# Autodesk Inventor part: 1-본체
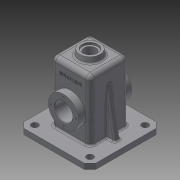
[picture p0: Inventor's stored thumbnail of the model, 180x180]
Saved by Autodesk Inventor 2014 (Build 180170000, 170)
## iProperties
Created: 2016-02
Part Number: 1-본체
Material: 일반
Document SubType Name: Modeling
Designer: 703-04
Density: 1 g/cm^3
Appearance: 기본값
Author: 703-04
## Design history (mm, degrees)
sketch "스케치1"
  geometry: L1 (-65, 65)-(65, 65); L2 (65, 65)-(65, -65); L3 (65, -65)-(-65, -65); L4 (-65, -65)-(-65, 65); 1 further point
  constraints: 8 end point, 2 parallel, 1 horizontal, 1 perpendicular
  dimensions: "d0" = 130 distance of L2.end L3.end; "d1" = 65 distance from line of point (0, 0) L4; "d2" = 65 distance from line of point (0, 0) L1; "d3" = 130 distance between parallel lines of L3 L1
extrude "돌출1" new body sketch "스케치1" distance "d4" = 10; taper "d5" = 0 deg
chamfer "모따기1" distance "d6" = 10; stored, may be unused: second distance "d7" = 2, angle "d8" = 45 deg
sketch "스케치2"
  geometry: L1 (-35, 35)-(35, 35); L2 (35, 35)-(35, -35); L3 (35, -35)-(-35, -35); L4 (-35, -35)-(-35, 35); 1 further point
  constraints: 8 end point, 2 parallel, 1 horizontal, 1 perpendicular
  dimensions: "d9" = 35 distance from line of point (0, 0) L1; "d10" = 70 distance between parallel lines of L3 L1; "d11" = 35 distance from line of point (0, 0) L4; "d12" = 70 distance between parallel lines of L2 L4
extrude "돌출2" join sketch "스케치2" distance "d13" = 110; taper "d14" = 0 deg
node "작업 평면1"
sketch "스케치4"
  geometry: L1 (0, 0)-(0, 131.974); L2 (-55, 0)-(55, 0) reference; L3 (-58, 55)-(58, 55); C1 r 27.5 at (0, 55)
  constraints: 4 end point, 1 centre point, 1 midpoint, 1 parallel, 1 perpendicular, 1 point on line
  dimensions: "d18" = 55 diameter of C1; "d19" = 55 distance between parallel lines of L2 L3
extrude "돌출3" join sketch "스케치4" stored distance "d20" = 96; taper "d21" = 0 deg
hole "구멍1" diameter "d24" = 32; stored, may be unused: countersink angle "d28" = 90 deg, drill point angle "d30" = 118 deg; dims "d22" = 10, "d23" = 10, "d25" = 6, "d26" = 4, "d27" = 2, "d29" = 8
sketch "스케치6"
  geometry: L1 (-55, 0)-(55, 0) reference; L2 (-30, 115)-(30, 115); L3 (30, 115)-(30, 0); L4 (30, 0)-(-30, 0); L5 (-30, 0)-(-30, 115); L6 (-35, 10)-(-35, 120) reference; L7 (35, 120)-(-35, 120) reference; L8 (35, 10)-(35, 120) reference; 1 further point
  constraints: 8 end point, 2 parallel, 1 horizontal, 1 perpendicular, 1 point on line
  dimensions: "d33" = 30 distance from line of point (0, 0) L5; "d34" = 30 distance from line of point (0, 0) L3; "d35" = 115 distance of L2.end L3.end
extrude "돌출4" cut sketch "스케치6" stored distance "d36" = 60; taper "d37" = 0 deg
sketch "스케치7"
  geometry: C1 r 20 at (0, 0); 1 further point
  constraints: 1 centre point, 1 coincident
  dimensions: "d38" = 40 diameter of C1
extrude "돌출5" join sketch "스케치7" distance "d39" = 10; taper "d40" = -10 deg
hole "구멍2" diameter "d43" = 21; stored, may be unused: countersink angle "d47" = 90 deg, drill point angle "d49" = 0 deg; dims "d41" = 10, "d42" = 10, "d44" = 6, "d45" = 28, "d46" = 4, "d48" = 15
sketch "스케치8"
  geometry: L1 (35, 10)-(35, 120) reference; L2 (35, 95.069)-(50, 10); L3 (-55, 10)-(55, 10) reference; L4 (65, 0)-(65, 10) reference; 1 further point
  constraints: 2 end point, 2 point on line
  dimensions: "d50" = 10 deg angle of L4 L2; "d51" = 15 distance from line of L2.end L4
feature "리브1" sketch "스케치8" dims "d52" = 1, "d53" = 10, "d54" = 0, "d55" = 0, "d56" = 1, "d57" = 1
node "작업축1"
node "작업축2"
node "작업 평면2"
sketch "스케치9"
  geometry: L1 (-51.5, 48)-(-51.5, 30) reference; L2 (-7.5, 30)-(-122.5, 30) reference; L3 (-148.5, 0)-(33.5, 0) reference; L4 (-67.5, -91)-(-67.5, 91) reference; L5 (-112.5, 35)-(-2.5, 35) reference; L6 (-51.5, 30)-(-40, 30); L7 (-40, 30)-(-47, 23); L8 (-47, 23)-(-51.5, 23); L9 (-51.5, 23)-(-51.5, 30); L10 (-40, 30)-(-51.5, 30); 1 further point
  constraints: 10 end point, 1 collinear, 1 parallel, 1 perpendicular, 1 point on line
  dimensions: "d59" = 7 distance between parallel lines of L8 L10; "d60" = 27.5 distance from line of L4 L6.end; "d61" = 135 deg angle of L7 L2
revolve "회전1" sketch "스케치9" stored, may be unused: angle "d62" = 90 deg
sketch "스케치10" dims "d63" = 45
  geometry: L1 (0, -81)-(0, 101) reference; C1 r 27.5 at (0, 0) reference; 3 further points
  constraints: 1 coincident, 1 point on line, 1 vertical alignment, 2 other
hole "구멍3" sketch "스케치10" at (0, 22.5) diameter "d64" = 3.242; stored, may be unused: countersink angle "d68" = 90 deg, drill point angle "d70" = 118 deg; dims "d65" = 8, "d66" = 28, "d67" = 4, "d69" = 10
fillet "모깎기1" dims "d71" = 0.5
fillet "모깎기2" dims "d72" = 0.5
fillet "모깎기3" dims "d76" = 0.5
fillet "모깎기4" dims "d77" = 0.5
sketch "스케치11"
  geometry: L1 (-50, 50)-(50, 50); L2 (50, 50)-(50, -50); L3 (50, -50)-(-50, -50); L4 (-50, -50)-(-50, 50); 5 further points
  constraints: 8 end point, 4 coincident, 2 parallel, 1 horizontal, 1 perpendicular
  dimensions: "d78" = 100 distance between parallel lines of L3 L1; "d79" = 50 distance from line of L1 point (0, 0); "d80" = 100 distance between parallel lines of L4 L2; "d81" = 50 distance from line of point (0, 0) L4
hole "구멍4" sketch "스케치11" at (-50, 50), (-50, -50), (50, -50), (50, 50) diameter "d82" = 12; stored, may be unused: countersink angle "d86" = 90 deg, drill point angle "d88" = 118 deg; dims "d83" = 8, "d84" = 28, "d85" = 4, "d87" = 10
fillet "모깎기5" dims "d89" = 8
fillet "모깎기6" dims "d90" = 8
fillet "모깎기7" dims "d91" = 3
fillet "모깎기8" dims "d92" = 3
chamfer "모따기2" distance "d93" = 1; stored, may be unused: second distance "d94" = 2, angle "d95" = 45 deg
fillet "모깎기9" dims "d96" = 3
fillet "모깎기10" dims "d97" = 3
fillet "모깎기11" dims "d98" = 3
fillet "모깎기12" dims "d99" = 3
fillet "모깎기13" dims "d100" = 3
fillet "모깎기14" dims "d101" = 3
node "작업 평면3"
sketch "스케치12"
  geometry: L1 (-17.83, 54.906)-(17.83, 54.906); L2 (17.83, 54.906)-(17.83, 35.094); L3 (17.83, 35.094)-(-17.83, 35.094); L4 (-17.83, 35.094)-(-17.83, 54.906); L5 (0, -81)-(0, 101) reference; L6 (-17.83, 45)-(17.83, 45); L7 (0, 54.906)-(0, 35.094); L8 (-48, 45)-(54, 45); L9 (-18.237, 75)-(18.237, 75) reference; 1 further point
  constraints: 6 end point, 4 midpoint, 2 collinear, 1 perpendicular, 2 other
  dimensions: "d103" = 30 distance between parallel lines of L8 L9
feature "엠보싱1" sketch "스케치12" dims "d104" = 0.5, "d105" = 0
node "솔리드1"
mirror "대칭1"
mirror "대칭2"
pattern_circular "원형 패턴1" dims angle "d74" = 360 deg
mirror "대칭3"
mirror "대칭4"
other parameters: "d17" = 0, "d58" = 90 deg
